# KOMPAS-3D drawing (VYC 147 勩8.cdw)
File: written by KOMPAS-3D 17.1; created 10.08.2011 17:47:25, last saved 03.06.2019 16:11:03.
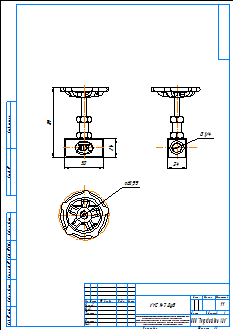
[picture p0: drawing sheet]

Sheet 1: A3, portrait

Title block, sheet 1: name: VYC 147 Ду8; material: Внимание! Данный продукт является объектом авторского права ООО «Торговый Дом АДЛ». / Запрещается изменение, копирование, распространение / (в том числе путем копирования на другие сайты и ресурсы в Интернете) / или любое иное использование информации и объектов без предварительного / согласия правообладателя (ООО «Торговый Дом АДЛ»).; scale: 1:1; sheets: 1; organisation: ООО "Торговый дом АДЛ"; sheet format: A3; stored path: \\adlc.lan\data\АДЛ_ПКД\3D-модели\Поставщики\VYC Industrial\VYC 147\KOMPAS 2D\VYC 147 Ду8.cdw

Views: Спереди 1, Проекционный вид 2, Проекционный вид 3
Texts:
  bsv
  adl
Dimensions and other numbers on the sheet: 50; 89; 24; 1/4; 63,99; 1:1; 1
